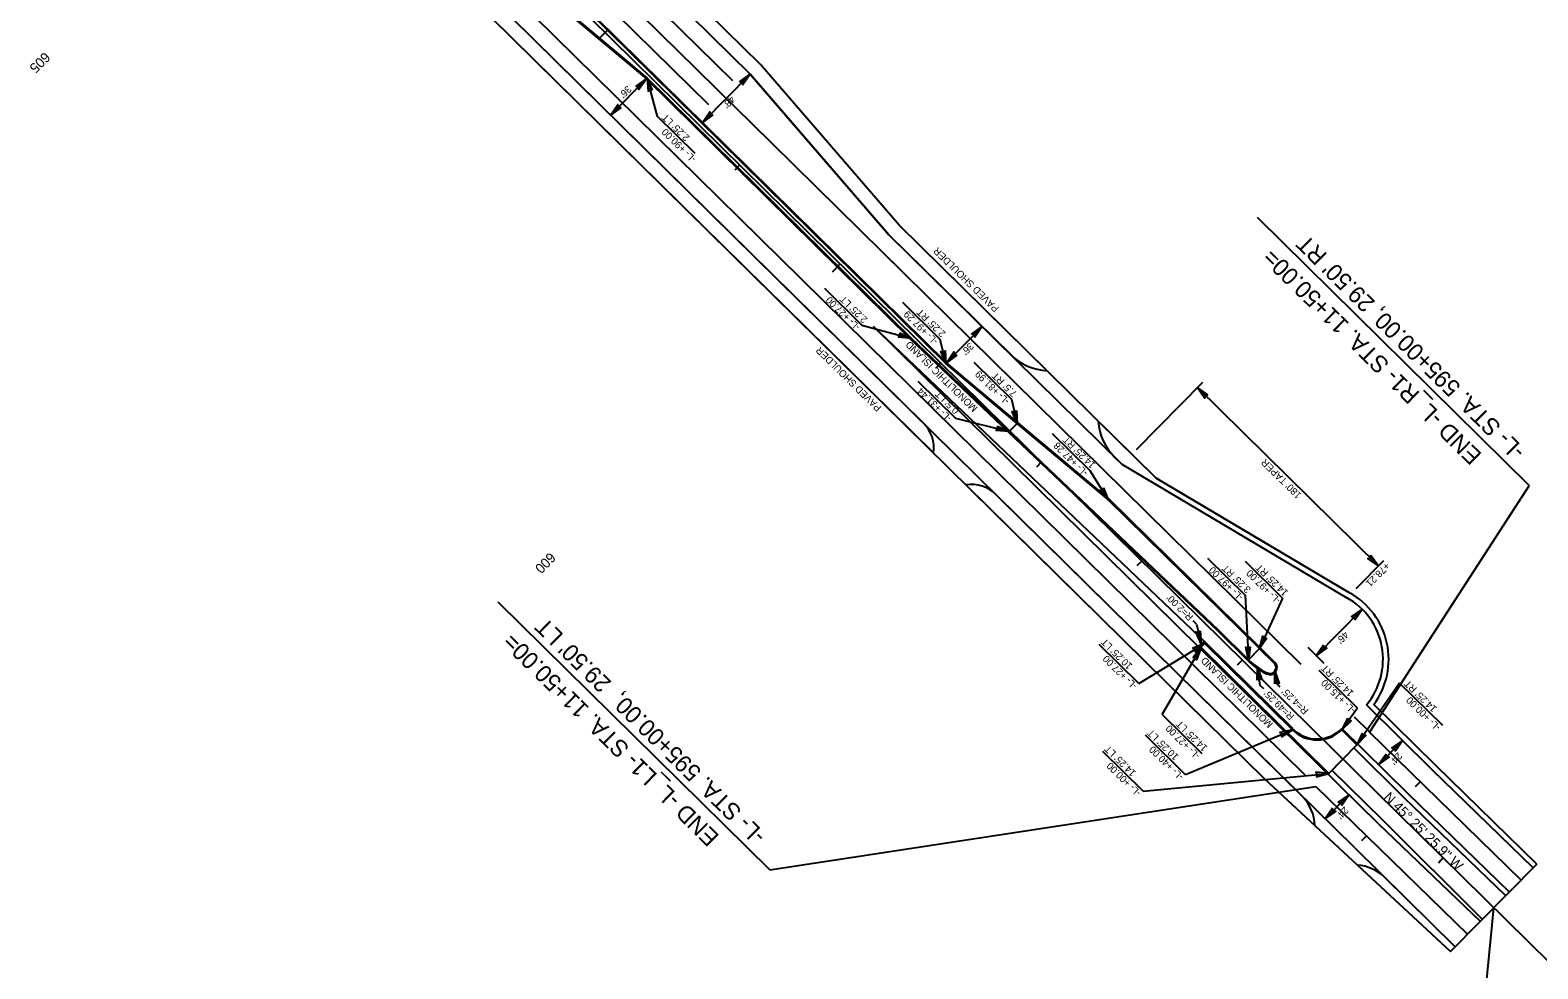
# Model space of a CAD drawing. Extents: x 1262642 to 1268358, y 767825 to 773481.
# Drawn here: x 1266714 to 1267782, y 771163 to 771829 of the extents above; entities that cross this region are included whole.
import ezdxf

# ---------------------------------------------------------------- set-up
doc = ezdxf.new("R2010")
doc.units = 0
for name, color, linetype in [('Prop Conc 1ft 6in Curb and Gutter', 7, 'Continuous'), ('Prop Conc 5in Monolithic Keyed In Island', 7, 'Continuous'), ('Prop Dimension', 7, 'Continuous'), ('Prop Dimension Text', 7, 'Continuous'), ('Prop EOT', 7, 'Continuous'), ('Prop Horizontal Alignment', 7, 'Continuous'), ('Prop Horizontal Alignment Direction Label', 7, 'Continuous'), ('Prop Horizontal Alignment Station Label', 7, 'Continuous'), ('Prop Horizontal Alignment Tick Label', 7, 'Continuous'), ('Prop Horizontal Alignment Tick Large', 7, 'Continuous'), ('Prop Horizontal Alignment Tick Small', 7, 'Continuous'), ('Prop Lane Lines', 7, 'Continuous'), ('Prop Paved Shoulder', 7, 'Continuous'), ('Prop Shade Light', 7, 'Continuous'), ('Prop Shade Medium', 7, 'Continuous'), ('Prop Terminator CELL', 7, 'Continuous')]:
    doc.layers.add(name, color=color, linetype=linetype)

msp = doc.modelspace()

# ---------------------------------------------------------------- linework, layer by layer
at = {"layer": 'Prop Conc 1ft 6in Curb and Gutter'}
for p, q in [((1267035.5, 771891.3), (1267117, 771822.8)), ((1267122.7, 771828.6), (1267080.5, 771870.1)), ((1267413.1, 771549.8), (1267407.4, 771544.1)), ((1267477.8, 771495.5), (1267413.1, 771549.8)), ((1267407.4, 771544.1), (1267555.7, 771403.3)), ((1267584.8, 771390.1), (1267477.7, 771495.6)), ((1267653.9, 771322), (1267633.9, 771301.7))]:
    msp.add_line(p, q, dxfattribs=at)
msp.add_arc((1267544.8, 771392.3), 2, 45.4239, 225.4239, dxfattribs=at)
at = {"layer": 'Prop Conc 5in Monolithic Keyed In Island'}
for p, q in [((1267117, 771822.8), (1267122.7, 771828.6)), ((1267362.5, 771592.3), (1267122.7, 771828.6)), ((1267117, 771822.8), (1267150.8, 771794.5)), ((1267338.1, 771609.9), (1267150.8, 771794.5)), ((1267407.4, 771544.1), (1267338.1, 771609.9)), ((1267413.1, 771549.8), (1267362.5, 771592.2)), ((1267577.1, 771382.2), (1267555.7, 771403.3)), ((1267633.9, 771301.7), (1267543.4, 771390.8)), ((1267608.2, 771332.6), (1267546.2, 771393.7)), ((1267577.1, 771382.2), (1267584.8, 771390.1)), ((1267595.4, 771379.6), (1267584.9, 771390)), ((1267643.2, 771332.5), (1267653.9, 771322))]:
    msp.add_line(p, q, dxfattribs=at)
for centre, radius, start, end in [((1267611.6, 771417.3), 49.3, 225.4615, 244.6497), ((1267592.3, 771376.7), 4.25, 244.6497, 45.4615), ((1267625.7, 771350.4), 25, 225.4239, 314.2779)]:
    msp.add_arc(centre, radius, start, end, dxfattribs=at)
at = {"layer": 'Prop Dimension'}
for p, q in [((1267544.4, 771578.7), (1267497.4, 771531.1)), ((1267669.1, 771448.9), (1267540.8, 771575.2)), ((1267672.6, 771452.4), (1267653, 771432.5))]:
    msp.add_line(p, q, dxfattribs=at)
at = {"layer": 'Prop Dimension Text'}
for p, q in [((1267223.8, 771797.4), (1267190.1, 771763.2)), ((1267150.3, 771794), (1267125, 771768.3)), ((1267184.8, 771741.2), (1267158.2, 771767.4)), ((1267276.6, 771645.6), (1267303.1, 771619.5)), ((1267331.8, 771635.7), (1267358.4, 771609.5)), ((1267363, 771592.8), (1267388.2, 771618.5)), ((1267382.4, 771593.2), (1267409, 771567)), ((1267342.8, 771579.8), (1267369.3, 771553.6)), ((1267438, 771542.5), (1267464.6, 771516.3)), ((1267548.1, 771454.3), (1267574.7, 771428.1)), ((1267574.6, 771452.1), (1267601.2, 771425.9)), ((1267625, 771385.1), (1267657.5, 771418.1)), ((1267540.3, 771407.4), (1267537.9, 771409.7)), ((1267540.3, 771407.4), (1267537.9, 771409.7)), ((1267540.3, 771407.4), (1267543.4, 771393.6)), ((1267499.3, 771365.4), (1267471.1, 771393.1)), ((1267630.7, 771379.5), (1267619.3, 771390.8)), ((1267585.4, 771363.9), (1267583.4, 771377)), ((1267597.3, 771365), (1267595.8, 771374.2)), ((1267654.3, 771348), (1267627.2, 771374.6)), ((1267587.8, 771361.6), (1267585.4, 771363.9)), ((1267599.6, 771362.7), (1267597.3, 771365)), ((1267714.8, 771335.5), (1267684.1, 771365.7)), ((1267515.8, 771343.5), (1267544, 771315.8)), ((1267532.5, 771300.6), (1267504, 771328.8)), ((1267502.4, 771289.1), (1267473.8, 771317.3)), ((1267686.1, 771325), (1267669.3, 771307.9)), ((1267648.2, 771286.5), (1267631.4, 771269.4))]:
    msp.add_line(p, q, dxfattribs=at)
for points in [[(1267158.2, 771767.4), (1267150.8, 771794.5)], [(1267303.1, 771619.5), (1267338.1, 771609.9)], [(1267358.4, 771609.5), (1267362.5, 771592.3)], [(1267409, 771567), (1267413.1, 771549.8)], [(1267369.3, 771553.6), (1267407.4, 771544.1)], [(1267464.6, 771516.3), (1267477.7, 771495.6)], [(1267574.7, 771428.1), (1267577.1, 771382.2)], [(1267601.2, 771425.9), (1267584.8, 771390.1)], [(1267499.3, 771365.4), (1267546.2, 771393.7)], [(1267515.8, 771343.5), (1267543.4, 771390.8)], [(1267684.1, 771365.7), (1267653.9, 771322)], [(1267654.3, 771348), (1267643.2, 771332.5)], [(1267532.3, 771300.9), (1267608.2, 771332.6)], [(1267502.4, 771289.1), (1267633.9, 771301.7)]]:
    msp.add_lwpolyline(points, dxfattribs=at)
for points in [[(1267548.3, 771570), (1267540.8, 771575.2), (1267546.2, 771567.7), (1267546.5, 771569.6)], [(1267663.7, 771456.3), (1267669.1, 771448.9), (1267661.5, 771454.1), (1267663.4, 771454.4)]]:
    msp.add_lwpolyline(points, close=True, dxfattribs=at)
at = {"layer": 'Prop EOT'}
for p, q in [((1267223.8, 771797.4), (1267078.8, 771940.2)), ((1267035, 771890.7), (1267150.3, 771794)), ((1267526, 771373.2), (1267021.5, 771870.3)), ((1267363, 771592.8), (1267081, 771870.7)), ((1267322.2, 771683.5), (1267223.8, 771797.4)), ((1267337.6, 771609.4), (1267150.3, 771794)), ((1267487.3, 771520.9), (1267322.2, 771683.5)), ((1267555.2, 771402.8), (1267337.6, 771609.4)), ((1267478.3, 771496.1), (1267363, 771592.8)), ((1267487.3, 771520.9), (1267646.7, 771426.2)), ((1267506.3, 771468.4), (1267478.3, 771496.1)), ((1267585.3, 771390.6), (1267506.3, 771468.4)), ((1267576.5, 771381.7), (1267555.2, 771402.8)), ((1267669.2, 771265.9), (1267542.9, 771390.3)), ((1267608.7, 771333.2), (1267546.7, 771394.2)), ((1267596, 771380.1), (1267585.3, 771390.6)), ((1267652.3, 771248.8), (1267526, 771373.2)), ((1267707.1, 771304.3), (1267660.6, 771350.2)), ((1267690.2, 771287.2), (1267643.2, 771333.6)), ((1267778.8, 771234.7), (1267707.1, 771304.3)), ((1267761.9, 771217.5), (1267690.2, 771287.2)), ((1267669.2, 771265.9), (1267741.4, 771196.7)), ((1267652.3, 771248.8), (1267723.6, 771178.6)), ((1267781.4, 771237.3), (1267720.3, 771175.3))]:
    msp.add_line(p, q, dxfattribs=at)
for centre, radius, start, end in [((1267622.4, 771382.5), 50, 319.7451, 60.9159), ((1267611.6, 771417.3), 50, 225.4615, 244.6497), ((1267592.3, 771376.7), 5, 244.6497, 45.4615), ((1267625.7, 771350.4), 24.3, 225.4239, 316.0146)]:
    msp.add_arc(centre, radius, start, end, dxfattribs=at)
at = {"layer": 'Prop Horizontal Alignment'}
for p, q in [((1268356.2, 770610), (1267043.4, 771903.5)), ((1267770.2, 771226), (1267662.7, 771330.9)), ((1267624.7, 771292.4), (1267732.4, 771187.5))]:
    msp.add_line(p, q, dxfattribs=at)
at = {"layer": 'Prop Horizontal Alignment Station Label'}
for p, q in [((1267776, 771505.8), (1267662.7, 771330.9)), ((1267237.8, 771233.2), (1267624.7, 771292.4)), ((1267732.7, 771019.4), (1267750.9, 771206.4))]:
    msp.add_line(p, q, dxfattribs=at)
for points in [[(1267776, 771505.8), (1267583.5, 771695.7)], [(1267237.8, 771233.2), (1267045.3, 771423.1)]]:
    msp.add_lwpolyline(points, dxfattribs=at)
at = {"layer": 'Prop Horizontal Alignment Tick Large'}
for p, q in [((1267287.7, 771662.8), (1267282.1, 771657.1)), ((1267643.9, 771311.8), (1267638.3, 771306.1))]:
    msp.add_line(p, q, dxfattribs=at)
at = {"layer": 'Prop Horizontal Alignment Tick Small'}
for p, q in [((1267216.5, 771733), (1267213, 771729.4)), ((1267358.9, 771592.6), (1267355.4, 771589)), ((1267430.2, 771522.4), (1267426.7, 771518.8)), ((1267501.4, 771452.2), (1267497.9, 771448.7)), ((1267572.6, 771382), (1267569.1, 771378.5)), ((1267698.6, 771295.8), (1267695.1, 771292.2)), ((1267660.7, 771257.3), (1267657.2, 771253.8)), ((1267715.1, 771241.7), (1267711.6, 771238.1))]:
    msp.add_line(p, q, dxfattribs=at)
at = {"layer": 'Prop Lane Lines'}
for p, q in [((1267211.5, 771792.6), (1267070.7, 771931.3)), ((1267194.7, 771775.5), (1267053.9, 771914.2)), ((1267239.4, 771748.3), (1267062.3, 771922.8)), ((1267260, 771652.2), (1267024.3, 771884.4)), ((1267614.4, 771378.8), (1267239.4, 771748.3)), ((1267329.9, 771659.1), (1267319.3, 771669.6)), ((1267617.1, 771300.3), (1267260, 771652.2)), ((1267542.9, 771390.3), (1267311.4, 771618.4)), ((1267546.7, 771394.2), (1267311.4, 771618.4)), ((1267662.8, 771331.1), (1267652.1, 771341.6))]:
    msp.add_line(p, q, dxfattribs=at)
at = {"layer": 'Prop Paved Shoulder'}
for p, q in [((1267231.1, 771804.2), (1267085.9, 771947.3)), ((1267519, 771366.1), (1267014.5, 771863.2)), ((1267329.5, 771690.4), (1267231.1, 771804.2)), ((1267511.6, 771511), (1267329.5, 771690.4)), ((1267511.6, 771511), (1267648.7, 771429.7)), ((1267588.3, 771297.8), (1267519, 771366.1)), ((1267709.9, 771307.2), (1267665.9, 771350.5)), ((1267687.4, 771284.4), (1267651.6, 771319.7)), ((1267672, 771268.7), (1267636.2, 771304)), ((1267781.4, 771237.3), (1267709.9, 771307.2)), ((1267720.3, 771175.3), (1267588.3, 771297.8)), ((1267759.3, 771214.8), (1267687.4, 771284.4)), ((1267742.9, 771198.2), (1267672, 771268.7))]:
    msp.add_line(p, q, dxfattribs=at)
msp.add_arc((1267622.4, 771382.5), 54, 323.6942, 60.9159, dxfattribs=at)
at = {"layer": 'Prop Shade Light'}
for p, q in [((1267231.1, 771804.2), (1267085.9, 771947.3)), ((1267078.8, 771940.2), (1267223.8, 771797.4)), ((1267346.7, 771549.9), (1267021.5, 771870.3)), ((1267014.5, 771863.2), (1267353.9, 771528.8)), ((1267223.8, 771797.4), (1267322.2, 771683.5)), ((1267329.5, 771690.4), (1267231.1, 771804.2)), ((1267434.4, 771587), (1267329.5, 771690.4)), ((1267322.2, 771683.5), (1267408.5, 771598.5)), ((1267511.6, 771511), (1267470.5, 771551.4)), ((1267482.4, 771525.7), (1267487.3, 771520.9)), ((1267487.3, 771520.9), (1267646.7, 771426.2)), ((1267648.7, 771429.7), (1267511.6, 771511)), ((1267376.8, 771506.2), (1267519, 771366.1)), ((1267526, 771373.2), (1267398, 771499.3)), ((1267615.1, 771285.5), (1267526, 771373.2)), ((1267519, 771366.1), (1267588.3, 771297.8)), ((1267660.6, 771350.2), (1267707.1, 771304.3)), ((1267709.9, 771307.2), (1267665.9, 771350.5)), ((1267707.1, 771304.3), (1267778.8, 771234.7)), ((1267781.4, 771237.3), (1267709.9, 771307.2)), ((1267588.3, 771297.8), (1267624, 771264.7)), ((1267654.2, 771236.6), (1267720.3, 771175.3)), ((1267778.8, 771234.7), (1267781.4, 771237.3)), ((1267723.6, 771178.6), (1267673.4, 771228.1)), ((1267720.3, 771175.3), (1267723.6, 771178.6))]:
    msp.add_line(p, q, dxfattribs=at)
for centre, radius, start, end in [((1267436.6, 771627), 40, 225.4239, 266.8334), ((1267329.1, 771532.1), 25, 352.2938, 45.4239), ((1267510.4, 771554.2), 40, 184.0143, 225.4239), ((1267380.5, 771481.5), 25, 45.4239, 98.554), ((1267622.4, 771382.5), 50, 319.7451, 60.9159), ((1267622.4, 771382.5), 54, 323.6942, 60.9159), ((1267594, 771264.1), 30, 1.0728, 45.4239), ((1267652.3, 771206.7), 30, 45.4383, 86.3244)]:
    msp.add_arc(centre, radius, start, end, dxfattribs=at)
at = {"layer": 'Prop Shade Medium'}
for p, q in [((1267117, 771822.8), (1267122.7, 771828.6)), ((1267122.7, 771828.6), (1267362.5, 771592.3)), ((1267150.8, 771794.5), (1267117, 771822.8)), ((1267338.1, 771609.9), (1267150.8, 771794.5)), ((1267407.4, 771544.1), (1267338.1, 771609.9)), ((1267362.5, 771592.3), (1267413.1, 771549.8)), ((1267413.1, 771549.8), (1267407.4, 771544.1)), ((1267633.9, 771301.7), (1267543.4, 771390.8)), ((1267546.2, 771393.7), (1267608.2, 771332.6)), ((1267584.8, 771390.1), (1267577.1, 771382.2)), ((1267595.3, 771379.7), (1267584.8, 771390.1)), ((1267643.2, 771332.5), (1267653.9, 771322)), ((1267653.9, 771322), (1267633.9, 771301.7))]:
    msp.add_line(p, q, dxfattribs=at)
for centre, radius, start, end in [((1267544.8, 771392.3), 2, 45.4239, 225.4239), ((1267611.6, 771417.3), 49.3, 225.4615, 244.6497), ((1267592.3, 771376.7), 4.25, 244.6497, 45.4615), ((1267625.7, 771350.4), 25, 225.4239, 314.2779)]:
    msp.add_arc(centre, radius, start, end, dxfattribs=at)
at = {"layer": 'Prop Terminator CELL'}
for points in [[(1267216.4, 771792), (1267223.8, 771797.4), (1267218.6, 771789.8), (1267218.2, 771791.7)], [(1267142.8, 771788.7), (1267150.3, 771794), (1267145.1, 771786.4), (1267144.7, 771788.4)], [(1267154.7, 771786.2), (1267150.8, 771794.5), (1267151.6, 771785.4), (1267152.9, 771786.9)], [(1267132.4, 771773.7), (1267125, 771768.3), (1267130.2, 771775.9), (1267130.5, 771774)], [(1267197.5, 771768.5), (1267190.1, 771763.2), (1267195.3, 771770.7), (1267195.6, 771768.8)], [(1267329.9, 771613.9), (1267338.1, 771609.9), (1267329, 771610.9), (1267330.5, 771612.1)], [(1267380.8, 771613.1), (1267388.2, 771618.5), (1267383, 771610.9), (1267382.7, 771612.8)], [(1267362, 771601.4), (1267362.5, 771592.3), (1267358.9, 771600.7), (1267360.7, 771600)], [(1267370.4, 771598.1), (1267363, 771592.8), (1267368.2, 771600.4), (1267368.5, 771598.5)], [(1267412.6, 771558.9), (1267413.1, 771549.8), (1267409.5, 771558.3), (1267411.3, 771557.5)], [(1267399.1, 771547.9), (1267407.4, 771544.1), (1267398.3, 771544.8), (1267399.8, 771546.1)], [(1267474.3, 771504), (1267477.7, 771495.6), (1267471.6, 771502.4), (1267473.6, 771502.3)], [(1267652.3, 771410.6), (1267657.5, 771418.1), (1267650, 771412.8), (1267652, 771412.5)], [(1267542.9, 771402.7), (1267543.4, 771393.6), (1267539.8, 771402.1), (1267541.6, 771401.3)], [(1267539.3, 771387.7), (1267546.2, 771393.7), (1267537.6, 771390.4), (1267539.4, 771389.6)], [(1267537.6, 771383.8), (1267543.4, 771390.8), (1267540.3, 771382.2), (1267539.5, 771384)], [(1267578.2, 771391.3), (1267577.1, 771382.2), (1267575.1, 771391.2), (1267576.7, 771390.1)], [(1267590, 771397.6), (1267584.8, 771390.1), (1267587.2, 771398.9), (1267588.1, 771397.2)], [(1267630.3, 771392.6), (1267625, 771385.1), (1267632.5, 771390.5), (1267630.6, 771390.8)], [(1267583.3, 771367.8), (1267583.4, 771377), (1267586.4, 771368.3), (1267584.6, 771369.2)], [(1267595.7, 771365.1), (1267595.8, 771374.2), (1267598.8, 771365.5), (1267597, 771366.4)], [(1267647.2, 771340.7), (1267643.2, 771332.5), (1267649.8, 771338.9), (1267647.8, 771338.9)], [(1267600.5, 771327.7), (1267608.2, 771332.6), (1267599.2, 771330.6), (1267600.9, 771329.5)], [(1267657.7, 771330.3), (1267653.9, 771322), (1267660.3, 771328.5), (1267658.4, 771328.5)], [(1267674.5, 771315.4), (1267669.3, 771307.9), (1267676.8, 771313.2), (1267674.8, 771313.5)], [(1267680.9, 771317.5), (1267686.1, 771325), (1267678.6, 771319.7), (1267680.6, 771319.4)], [(1267625, 771299.3), (1267633.9, 771301.7), (1267624.7, 771302.5), (1267626, 771301)], [(1267643, 771279), (1267648.2, 771286.5), (1267640.7, 771281.2), (1267642.7, 771280.9)], [(1267636.6, 771276.9), (1267631.4, 771269.4), (1267638.9, 771274.7), (1267636.9, 771275)]]:
    msp.add_lwpolyline(points, close=True, dxfattribs=at)

# ---------------------------------------------------------------- texts
at = {"layer": 'Prop Dimension'}
for s, p in [('PAVED SHOULDER', (1267400.6, 771631.7)), ('PAVED SHOULDER', (1267317.3, 771561.3)), ('MONOLITHIC ISLAND', (1267385.4, 771560.9)), ("R=2.00'", (1267538.3, 771412.9)), ('MONOLITHIC ISLAND', (1267594.7, 771336.9)), ("R=49.25'", (1267609.9, 771342.5)), ("R=4.25'", (1267619.9, 771346.5))]:
    msp.add_text(s, height=5, rotation=135.4239, dxfattribs=at).set_placement(p)
at = {"layer": 'Prop Dimension Text'}
for s, rotation, p in [("36'", 225.4239, (1267136.8, 771789.6)), ("48'", 225.4239, (1267210.2, 771782.4)), ("2.25' LT", 135.4239, (1267181.4, 771752.8)), ('-L- +90.00', 135.4239, (1267186, 771737.8)), ('-L- +27.00', 135.4239, (1267302.3, 771618.6)), ("2.25' LT", 135.4239, (1267307.5, 771623.9)), ('-L- +97.29', 135.4239, (1267357.5, 771608.6)), ("2.25' RT", 135.4239, (1267362.8, 771613.9)), ("36'", 225.4239, (1267379.4, 771607.4)), ('-L- +81.99', 135.4239, (1267408.1, 771566.1)), ("7.5' RT", 135.4239, (1267413.4, 771571.5)), ('-L- +31.44', 135.4239, (1267367.1, 771554.1)), ("0.5' LT", 135.4239, (1267372.4, 771559.4)), ("14.25' RT", 135.4239, (1267469, 771520.8)), ('-L- +47.28', 135.4239, (1267463.7, 771515.4)), ("180' TAPER", 135.4239, (1267615, 771499.4)), ('-L- +97.00', 135.4239, (1267573.8, 771427.2)), ("3.25' RT", 135.4239, (1267579.1, 771432.5)), ('-L- +97.00', 135.4239, (1267600.3, 771425)), ("14.25' RT", 135.4239, (1267605.6, 771430.3)), ('+78.21', 225.4239, (1267674.3, 771451.6)), ("46'", 225.4239, (1267645.1, 771402.8)), ("10.25' LT", 135.4239, (1267495.2, 771378.3)), ('-L- +27.00', 135.4239, (1267498.6, 771364.3)), ("14.25' RT", 135.4239, (1267652, 771359)), ('-L- +15.00', 135.4239, (1267653.3, 771347.2)), ("14.25' RT", 135.4239, (1267710.9, 771348)), ('-L- +00.00', 135.4239, (1267713.6, 771334.9)), ("14.25' LT", 135.4239, (1267548.4, 771320.2)), ("10.25' LT", 135.4239, (1267528, 771313.9)), ('-L- +27.00', 135.4239, (1267543.1, 771314.9)), ("14.25' LT", 135.4239, (1267497.7, 771302.5)), ('-L- +40.00', 135.4239, (1267531.4, 771300)), ("24'", 225.4239, (1267683, 771317)), ('-L- +00.00', 135.4239, (1267501.3, 771288.4)), ("24'", 225.4239, (1267645.1, 771278.5))]:
    msp.add_text(s, height=5, rotation=rotation, dxfattribs=at).set_placement(p)
at = {"layer": 'Prop Horizontal Alignment Direction Label'}
msp.add_text('N 45%%d 25\' 25.9" W', height=7, rotation=315.4239, dxfattribs=at).set_placement((1267672.3, 771284.1))
at = {"layer": 'Prop Horizontal Alignment Station Label'}
for s, p in [("-L- STA. 595+00.00, 29.50' RT", (1267773.9, 771531.1)), ('END -L_R1- STA. 11+50.00=', (1267743, 771527.9)), ("-L- STA. 595+00.00,  29.50' LT", (1267235.8, 771258.4)), ('END -L_L1- STA. 11+50.00=', (1267202.6, 771257.4))]:
    msp.add_text(s, height=12, rotation=135.4239, dxfattribs=at).set_placement(p)
at = {"layer": 'Prop Horizontal Alignment Tick Label'}
for s, rotation, p in [('605', 224.6154, (1266723.7, 771813.5)), ('600', 225.4239, (1267081.8, 771458.8))]:
    msp.add_text(s, height=7, rotation=rotation, dxfattribs=at).set_placement(p)

doc.saveas('drawing.dxf')
